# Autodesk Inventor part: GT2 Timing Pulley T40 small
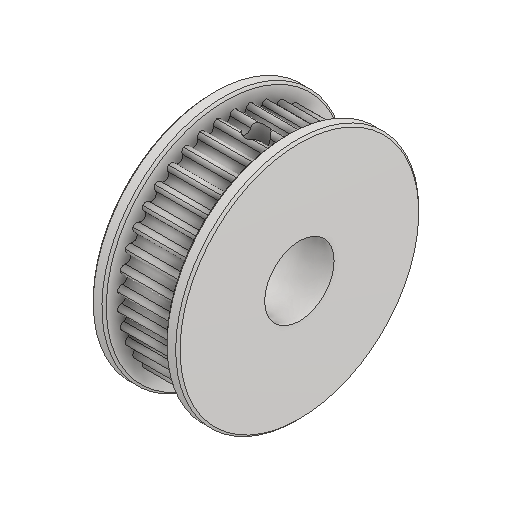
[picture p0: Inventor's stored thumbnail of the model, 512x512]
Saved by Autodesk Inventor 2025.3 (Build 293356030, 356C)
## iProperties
Created: 2022-06
Part Number: GT2 Timing Pulley T40 small
Material: Steel, Mild
Document SubType Name: Modeling
Designer: 18907419
Density: 7.85 g/cm^3
Appearance: Default
Sending System: Autodesk Inventor 2019
Preprocessor: ST-DEVELOPER v17.2
Title: D:\Documents\Niels Hermans\3D printer\GrabCAD\GT2 Timing Pulley T40.stp
Author: Niels
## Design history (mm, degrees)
body "Solid1"
sketch "Schizzo1"
  geometry: C1 r 13.75 at (0, 0) reference; 2 further points
  constraints: 1 coincident
hole "Foro1" sketch "Schizzo1" at (0, 0) diameter "d0" = 8; stored, may be unused: countersink angle "d4" = 89.9544 deg, drill point angle "d6" = 118 deg; dims "d1" = 6, "d2" = 10.4, "d3" = 2, "d5" = 8
node "Piano di lavoro1"
node "Piano di lavoro2"
node "Piano di lavoro3"
sketch "Schizzo3"
  geometry: 2 further points
  constraints: 1 other
hole "Foro2" sketch "Schizzo3" at (-5, 0) diameter "d10" = 2.459; stored, may be unused: countersink angle "d14" = 90 deg, drill point angle "d16" = 118 deg; dims "d11" = 10, "d12" = 4, "d13" = 2, "d15" = 8
node "Solido1"
